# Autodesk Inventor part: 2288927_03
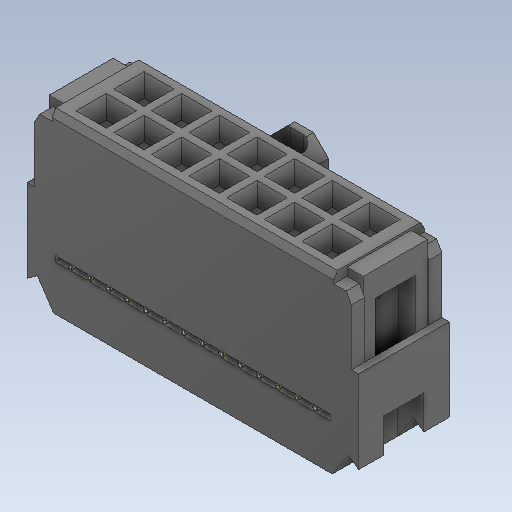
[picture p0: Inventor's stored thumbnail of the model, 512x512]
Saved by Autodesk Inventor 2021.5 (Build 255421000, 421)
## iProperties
Created: 2026-04
Part Number: 2288927_03
Checked By: TraceParts S.A.
Material: Generic
Catalog Web Link: www.traceparts.com
Document SubType Name: Modeling
Designer: TraceParts
Density: 1 g/cm^3
Appearance: Default
Company: TraceParts S.A.
Author: TraceParts
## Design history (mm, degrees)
feature "2288927_03.ipt"
body "Solid1"
